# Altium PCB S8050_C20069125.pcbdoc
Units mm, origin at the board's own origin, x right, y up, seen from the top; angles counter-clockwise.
Board outline 15.75 x 15.66 mm, 2 copper layers (Top Layer, Bottom Layer), stack 0 mm thick; 1 components, 0 nets, 3 pads, 0 vias.
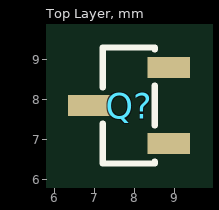
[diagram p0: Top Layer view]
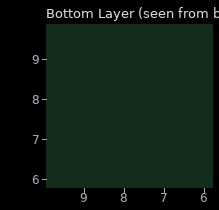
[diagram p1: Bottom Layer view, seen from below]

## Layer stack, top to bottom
Top Layer: signal copper (thickness not stored)
Bottom Layer: signal copper (thickness not stored)

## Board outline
15.75,0 0,0 0,15.66 15.75,15.66

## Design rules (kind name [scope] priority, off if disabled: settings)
PasteMaskExpansion "Paste Mask Expansion" [All] p1: expansion=0
SolderMaskExpansion "Solder Mask Expansion" [IsVia] p1: expansion=-25.4 istentingtop=TRUE
SolderMaskExpansion "Solder Mask Expansion" [All] p2: expansion=0.051 istentingtop=FALSE

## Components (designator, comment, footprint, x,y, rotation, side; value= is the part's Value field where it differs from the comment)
Q? "S8050" SOT-23-3_L2.9-W1.3-P1.90-LS2.3-BR 7.875,7.86 r0 top

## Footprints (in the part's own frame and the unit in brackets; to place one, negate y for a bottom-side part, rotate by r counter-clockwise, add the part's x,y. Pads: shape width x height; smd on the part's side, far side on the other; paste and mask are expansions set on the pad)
SOT-23-3_L2.9-W1.3-P1.90-LS2.3-BR [mm]
  rect 1.07x0.532 smd: 1(0.99,-0.95) 2(0.99,0.95) 3(-0.99,0)
  silkscreen extent -0.66,-1.45 0.64,1.45

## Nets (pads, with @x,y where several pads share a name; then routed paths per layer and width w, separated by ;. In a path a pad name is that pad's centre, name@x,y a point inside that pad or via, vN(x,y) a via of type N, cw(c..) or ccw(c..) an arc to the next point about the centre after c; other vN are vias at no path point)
pads on no net: Q?.1 Q?.2 Q?.3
